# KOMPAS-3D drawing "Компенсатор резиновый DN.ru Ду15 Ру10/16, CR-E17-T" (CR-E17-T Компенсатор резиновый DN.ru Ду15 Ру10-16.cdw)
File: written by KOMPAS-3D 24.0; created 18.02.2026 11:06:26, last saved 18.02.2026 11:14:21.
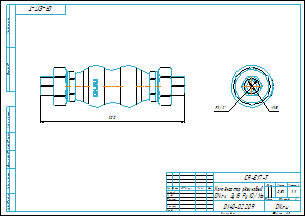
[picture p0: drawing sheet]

Document properties: Типовые: Типовые; Автор: DN.RU; Форматы листов документа: A3; Полное имя файла: CR-E17-T Компенсатор резиновый DN.ru Ду15 Ру10-16.m3d; Масса: 0.52; Наименование: Компенсатор резиновый DN.ru Ду15 Ру10/16; Количество листов документа: 1; Комментарий: D140-02209; Примечание: D140-02209

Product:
- Body: Твердое тело1  | qty 1
    Масса: 2.112779
- Part/product: Компенсатор резиновый DN.ru Ду15 Ру10/16  | designation CR-E17-T
    Масса: 0.52
    Раздел спецификации: Прочие изделия
    Форматы листов документа: A3
    Комментарий: D140-02209
    Примечание: D140-02209
    additional columns: Типовые

Views: Вид 1, Проекционный вид 2
Referenced files in D:\Работа\Компенсаторы\CR-Е17-T Компенсатор резиновый DN.ru Ду15-80\DN15\: CR-E17-T Компенсатор резиновый DN.ru Ду15 Ру10-16.m3d, CR-E17-T Компенсатор резиновый DN.ru Ду15 Ру10-16.cdw
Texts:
  Линейный размер
  CR-E17-T
  Пользовательская
  Диаметральный размер
  Компенсатор резиновый
  DN.ru Ду15 Ру10/16
  Твердое тело1
  Компенсатор резиновый DN.ru Ду15 Ру10/16
  CR-E17-T Компенсатор резиновый DN.ru Ду15 Ру10/16
Dimensions and other numbers on the sheet: 0; 3; 2; 4; 200; 15; 1:1; 1; 0,52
